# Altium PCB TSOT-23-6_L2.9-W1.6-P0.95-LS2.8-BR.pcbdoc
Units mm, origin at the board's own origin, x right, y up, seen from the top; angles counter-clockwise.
Board outline 16.1 x 16.04 mm, 2 copper layers (Top Layer, Bottom Layer), stack 0 mm thick; 1 components, 0 nets, 6 pads, 0 vias.
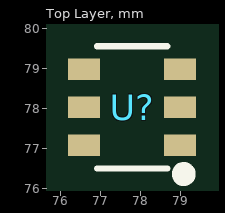
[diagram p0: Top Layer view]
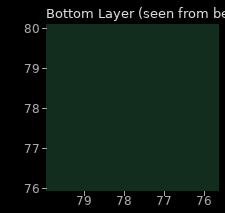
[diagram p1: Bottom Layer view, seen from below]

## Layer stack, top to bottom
Top Layer: signal copper (thickness not stored)
Bottom Layer: signal copper (thickness not stored)

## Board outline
85.95,69.85 69.85,69.85 69.85,85.895 85.95,85.895

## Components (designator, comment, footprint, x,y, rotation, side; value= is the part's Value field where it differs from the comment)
U? "" TSOT-23-6_L2.9-W1.6-P0.95-LS2.8-BR 77.8,78.019 r0 top

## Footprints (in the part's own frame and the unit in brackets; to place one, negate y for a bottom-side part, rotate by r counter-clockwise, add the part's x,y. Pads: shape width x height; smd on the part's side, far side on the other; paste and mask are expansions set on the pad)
TSOT-23-6_L2.9-W1.6-P0.95-LS2.8-BR [mm]
  rect 0.8x0.532 smd: 1(1.2,-0.95) 2(1.2,0) 3(1.2,0.95) 4(-1.2,0.95) 5(-1.2,0) 6(-1.2,-0.95)
  silkscreen extent -0.88,-1.82 1.44,1.53

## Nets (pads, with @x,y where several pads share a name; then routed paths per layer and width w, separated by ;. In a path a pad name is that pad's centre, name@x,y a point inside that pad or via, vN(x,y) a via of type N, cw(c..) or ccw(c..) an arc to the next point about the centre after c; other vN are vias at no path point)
pads on no net: U?.1 U?.2 U?.3 U?.4 U?.5 U?.6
